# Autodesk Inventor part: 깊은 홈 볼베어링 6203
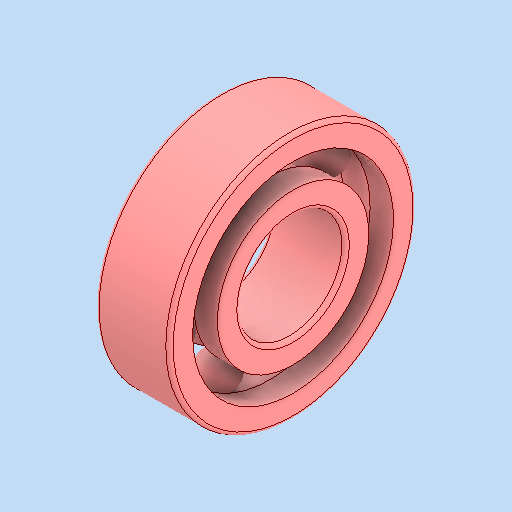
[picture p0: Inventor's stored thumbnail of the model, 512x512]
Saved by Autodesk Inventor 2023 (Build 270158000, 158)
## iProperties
Created: 2024-09
Part Number: 깊은 홈 볼베어링 6203
Material: 강철, 연강
Description: 깊은 그루브 볼 베어링
Document SubType Name: Modeling
Designer: asung
Density: 7.85 g/cm^3
Appearance: 기본값
Author: jhkim
Sending System: Autodesk Inventor 2025
Preprocessor: ST-DEVELOPER v20
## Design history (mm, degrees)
feature "Solid1"
feature "Solid1:1"
feature "Solid1:2"
feature "Solid1:3"
feature "Solid1:4"
feature "Solid1:5"
feature "Solid1:6"
feature "Solid1:7"
feature "Solid1:8"
node "솔리드1"
node "솔리드2"
node "솔리드3"
node "솔리드4"
node "솔리드5"
node "솔리드6"
node "솔리드7"
node "솔리드8"
node "솔리드9"
